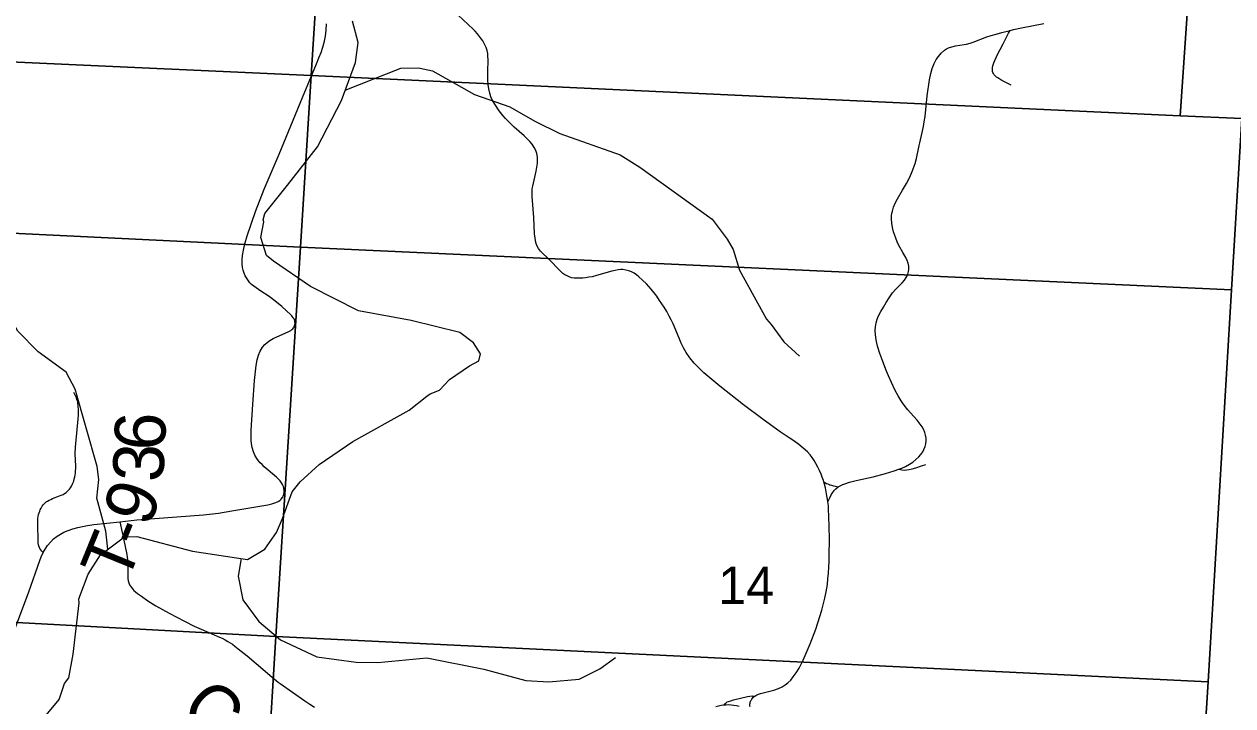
# Model space of a CAD drawing. Extents: x 0 to 34, y 0 to 22.
# Drawn here: x 25.758 to 27.11, y 15.745 to 16.507 of the extents above; entities that cross this region are included whole.
import ezdxf

# ---------------------------------------------------------------- set-up
doc = ezdxf.new("R2010")
doc.units = 0
for name, color, linetype in [('GM_X_County_Road', 7, 'Continuous'), ('GM_X_County_Road_Text', 7, 'Continuous'), ('GM_X_Minor_River', 7, 'Continuous'), ('GM_X_Section', 7, 'Continuous'), ('GM_X_Section_Text', 7, 'Continuous'), ('GM_X_State_Route', 7, 'Continuous'), ('GM_X_Township_Road', 7, 'Continuous'), ('GM_X_Township_Road_Text', 7, 'Continuous')]:
    doc.layers.add(name, color=color, linetype=linetype)

msp = doc.modelspace()

# ---------------------------------------------------------------- linework, layer by layer
at = {"layer": 'GM_X_County_Road'}
for points in [[(26.6568, 15.9731), (26.659, 15.9775), (26.6606, 15.9808), (26.6618, 15.9828), (26.6632, 15.9846), (26.6643, 15.986), (26.6658, 15.9876), (26.6682, 15.9896), (26.6705, 15.9909), (26.6735, 15.9923), (26.6756, 15.9931), (26.6808, 15.9949), (26.6886, 15.9969), (26.7073, 16.001), (26.7212, 16.0045), (26.731, 16.0075), (26.7361, 16.0094), (26.7394, 16.0106), (26.7436, 16.0126), (26.748, 16.0149), (26.7517, 16.0174), (26.7551, 16.0201), (26.7583, 16.0231), (26.7609, 16.0259), (26.763, 16.029), (26.7642, 16.0313), (26.7656, 16.0348), (26.7664, 16.0379), (26.7667, 16.041), (26.7666, 16.0442), (26.7661, 16.0473), (26.7652, 16.0504), (26.764, 16.0533), (26.7622, 16.0566), (26.7589, 16.0612), (26.7566, 16.0641), (26.7492, 16.0725), (26.7463, 16.0758), (26.7422, 16.0811), (26.7404, 16.0835), (26.7388, 16.0859), (26.7352, 16.0916), (26.7321, 16.0975), (26.7279, 16.1064), (26.7247, 16.1138), (26.7225, 16.119), (26.7181, 16.1299), (26.7149, 16.1386), (26.7124, 16.1469), (26.7107, 16.1541), (26.7099, 16.1596), (26.7097, 16.1645), (26.71, 16.1687), (26.7107, 16.1729), (26.7118, 16.177), (26.7134, 16.181), (26.716, 16.1858), (26.7188, 16.1905), (26.722, 16.1958), (26.7253, 16.201), (26.7292, 16.2064), (26.7327, 16.2106), (26.7364, 16.2145), (26.7398, 16.2178), (26.7426, 16.2209), (26.7444, 16.2236), (26.7455, 16.2257), (26.7461, 16.2276), (26.7468, 16.2303), (26.7472, 16.2326), (26.7472, 16.2363), (26.7465, 16.2399), (26.7455, 16.2427), (26.7439, 16.246), (26.7405, 16.2518), (26.7372, 16.2576), (26.7348, 16.2626), (26.7323, 16.2689), (26.7303, 16.2747), (26.7291, 16.2795), (26.7283, 16.2844), (26.728, 16.2892), (26.7281, 16.2929), (26.7283, 16.2953), (26.7289, 16.2977), (26.7303, 16.3024), (26.7321, 16.3069), (26.7347, 16.3118), (26.7404, 16.3213), (26.7448, 16.3288), (26.7485, 16.336), (26.7512, 16.3423), (26.7543, 16.3512), (26.7557, 16.3566), (26.7589, 16.3711), (26.7595, 16.3742), (26.7623, 16.3857), (26.7638, 16.3924), (26.7645, 16.3979), (26.7655, 16.4037), (26.7679, 16.4269), (26.7703, 16.4445), (26.772, 16.4517), (26.7735, 16.4573), (26.7758, 16.463), (26.778, 16.4673), (26.7804, 16.4708), (26.7834, 16.4746), (26.787, 16.4777), (26.7896, 16.4793), (26.7917, 16.4803), (26.7952, 16.4816), (26.7993, 16.4826), (26.8091, 16.484), (26.8116, 16.4845), (26.8157, 16.4856), (26.8193, 16.4868), (26.8346, 16.4926), (26.8395, 16.4943), (26.8448, 16.4959), (26.8511, 16.4976), (26.8605, 16.4999), (26.8644, 16.5009), (26.8734, 16.5027), (26.8981, 16.5077)], [(26.6523, 15.9951), (26.6553, 15.9935), (26.6577, 15.9925), (26.6591, 15.9919), (26.6608, 15.9914), (26.6631, 15.9908), (26.6654, 15.9903), (26.6682, 15.9896)], [(25.865, 15.9506), (25.8676, 15.9386), (25.8706, 15.9247), (25.8729, 15.9142), (25.8734, 15.9112), (25.8738, 15.9086), (25.874, 15.9056), (25.8741, 15.9025), (25.8741, 15.8897), (25.8742, 15.8871), (25.8745, 15.8846), (25.8751, 15.8822), (25.8759, 15.8803), (25.8769, 15.8785), (25.8781, 15.877), (25.8795, 15.8754), (25.8809, 15.8739), (25.8826, 15.8724), (25.8847, 15.8706), (25.8892, 15.8673), (25.8964, 15.8624), (25.9053, 15.8568), (25.9204, 15.8483), (25.9373, 15.8395), (25.9484, 15.834), (25.956, 15.8304), (25.9707, 15.8243), (25.9741, 15.8229), (25.9767, 15.8218), (25.9795, 15.8204), (25.9828, 15.8187), (25.986, 15.8169), (25.9886, 15.8153), (25.991, 15.8137), (25.9938, 15.8116), (25.9973, 15.8087), (26.0074, 15.8007), (26.0177, 15.7921), (26.0355, 15.7768), (26.0376, 15.775), (26.0398, 15.7732), (26.0421, 15.7715), (26.0442, 15.7699), (26.072, 15.7504), (26.0776, 15.7466), (26.0826, 15.7435)], [(26.5316, 15.744), (26.5344, 15.7449), (26.5373, 15.7455), (26.5405, 15.7459), (26.5428, 15.7461), (26.5454, 15.7462), (26.5486, 15.7461), (26.5517, 15.7457), (26.5547, 15.7452), (26.5576, 15.7446)], [(26.5405, 15.7459), (26.5418, 15.7474), (26.5429, 15.7483), (26.5443, 15.7492), (26.5456, 15.7498), (26.5482, 15.7506), (26.5511, 15.7514), (26.5668, 15.7552), (26.5694, 15.7557), (26.5721, 15.756), (26.5752, 15.7558)]]:
    msp.add_lwpolyline(points, dxfattribs=at)
at = {"layer": 'GM_X_Minor_River'}
for points in [[(25.779, 15.73), (25.7971, 15.7521), (25.8031, 15.77), (25.808, 15.7761), (25.8129, 15.8027), (25.8197, 15.8601), (25.8193, 15.8643), (25.8298, 15.892), (25.8434, 15.9137), (25.8702, 15.9339), (25.8842, 15.934), (25.9462, 15.9178), (26.0079, 15.9085), (26.0271, 15.9199), (26.0403, 15.9386), (26.0471, 15.9542), (26.0577, 15.9842), (26.0668, 15.9953), (26.0879, 16.0147), (26.1257, 16.0403), (26.1888, 16.0754), (26.2084, 16.091), (26.2122, 16.0937), (26.2224, 16.0979), (26.2337, 16.1097), (26.256, 16.125), (26.2666, 16.1307), (26.2685, 16.1383), (26.2605, 16.1508), (26.2454, 16.1622), (26.191, 16.1757), (26.132, 16.1866), (26.0783, 16.2138), (26.037, 16.2418), (26.0291, 16.2483), (26.0227, 16.2684), (26.026, 16.2859), (26.0253, 16.2882), (26.0272, 16.2954), (26.0525, 16.327), (26.0861, 16.3697), (26.1129, 16.4214), (26.1287, 16.464), (26.1317, 16.4865), (26.1253, 16.5104)], [(25.8517, 15.9199), (25.8493, 15.9401), (25.8395, 15.9769), (25.8416, 15.9977), (25.8398, 16.0125), (25.8152, 16.0987), (25.8052, 16.1177), (25.7738, 16.1407), (25.751, 16.1638), (25.7277, 16.2055), (25.7205, 16.2183), (25.6953, 16.2461), (25.676, 16.2569), (25.6365, 16.2878), (25.5914, 16.334), (25.575, 16.3421), (25.5444, 16.3674), (25.5396, 16.3713), (25.527, 16.3926), (25.5105, 16.4079), (25.4978, 16.4251), (25.462, 16.4531)], [(26.1172, 16.4331), (26.1792, 16.4577), (26.1992, 16.4582), (26.2146, 16.4547), (26.2618, 16.4282), (26.3011, 16.4144), (26.3293, 16.3983), (26.3569, 16.3845), (26.4246, 16.3607), (26.4465, 16.3471), (26.5275, 16.2891), (26.5442, 16.2666), (26.551, 16.2549), (26.5579, 16.2319), (26.5883, 16.1771), (26.5934, 16.1712), (26.6076, 16.1518), (26.6249, 16.1357)], [(26.0009, 15.9095), (25.9976, 15.8898), (26.0026, 15.8632), (26.0204, 15.8393), (26.0448, 15.8185), (26.0854, 15.7996), (26.1294, 15.7936), (26.1537, 15.7933), (26.2083, 15.7987), (26.272, 15.7859), (26.3191, 15.7731), (26.3449, 15.7717), (26.3786, 15.7748), (26.4017, 15.7862), (26.4192, 15.7988)]]:
    msp.add_lwpolyline(points, dxfattribs=at)
at = {"layer": 'GM_X_Section'}
for points in [[(27.1786, 17.2427), (27.1198, 16.4014), (27.0508, 16.4046), (27.0684, 16.6654), (27.1074, 17.2433)], [(25.1282, 16.7564), (25.9113, 16.7209), (26.0957, 16.7125), (26.0791, 16.4497), (25.1102, 16.4936)], [(26.0957, 16.7125), (26.5448, 16.6908), (27.0684, 16.6654), (27.0508, 16.4046), (26.0791, 16.4497)], [(25.1102, 16.4936), (26.0791, 16.4497), (26.067, 16.2576), (25.0369, 16.3074), (25.0486, 16.498)], [(27.0508, 16.4046), (27.1198, 16.4014), (27.1082, 16.21), (26.067, 16.2576), (26.0791, 16.4497)], [(25.0369, 16.3074), (26.067, 16.2576), (26.0395, 15.8225), (25.0112, 15.8778)], [(26.067, 16.2576), (27.1082, 16.21), (27.0819, 15.7717), (26.0395, 15.8225)], [(26.0395, 15.8225), (26.0137, 15.3999), (24.9883, 15.4512), (25.0112, 15.8778)], [(27.0819, 15.7717), (27.0537, 15.3245), (26.2501, 15.3844), (26.0137, 15.3999), (26.0395, 15.8225)]]:
    msp.add_lwpolyline(points, close=True, dxfattribs=at)
msp.add_lwpolyline([(27.7971, 15.2681), (27.0537, 15.3245), (27.0819, 15.7717), (27.1082, 16.21), (27.1198, 16.4014)], dxfattribs=at)
at = {"layer": 'GM_X_State_Route'}
for points in [[(26.5698, 15.7439), (26.5697, 15.745), (26.5696, 15.746), (26.5697, 15.7469), (26.5698, 15.7479), (26.57, 15.7489), (26.5703, 15.7498), (26.5707, 15.7507), (26.5712, 15.7516), (26.5718, 15.7525), (26.5725, 15.7535), (26.5734, 15.7544), (26.5743, 15.7552), (26.5752, 15.7558), (26.5764, 15.7566), (26.5775, 15.7572), (26.5785, 15.7576), (26.5793, 15.7579), (26.5804, 15.7583), (26.5815, 15.7586), (26.5963, 15.7625), (26.6017, 15.7644), (26.6057, 15.7662), (26.609, 15.7682), (26.612, 15.7706), (26.6152, 15.7737), (26.618, 15.7771), (26.6213, 15.7817), (26.6245, 15.7871), (26.629, 15.796), (26.637, 15.8143), (26.6433, 15.8305), (26.65, 15.8518), (26.6534, 15.8652), (26.6549, 15.8724), (26.6562, 15.8806), (26.6569, 15.8867), (26.6574, 15.893), (26.6579, 15.8998), (26.6582, 15.9062), (26.6584, 15.9123), (26.6585, 15.9319), (26.658, 15.9571), (26.6576, 15.9639), (26.6573, 15.9684), (26.6568, 15.9731), (26.6564, 15.976), (26.6558, 15.9798), (26.655, 15.9841), (26.654, 15.9886), (26.6529, 15.9927), (26.6523, 15.9951), (26.6518, 15.9966), (26.6505, 16.0004), (26.6492, 16.0038), (26.6474, 16.0078), (26.6456, 16.0117), (26.6434, 16.0158), (26.6415, 16.0192), (26.6393, 16.0224), (26.6369, 16.0256), (26.6339, 16.0288), (26.6293, 16.0331), (26.6244, 16.037), (26.6188, 16.041), (26.6136, 16.0444), (26.6033, 16.0513), (26.5843, 16.0651), (26.5626, 16.0813), (26.536, 16.1022), (26.5182, 16.1173), (26.5125, 16.1226), (26.5073, 16.128), (26.5024, 16.1339), (26.4982, 16.1399), (26.4953, 16.1449), (26.4928, 16.1502), (26.4904, 16.1558), (26.4837, 16.1719), (26.4815, 16.1765), (26.4795, 16.1805), (26.4766, 16.1856), (26.4737, 16.1904), (26.4712, 16.1944), (26.4687, 16.1981), (26.4654, 16.2028), (26.4625, 16.2067), (26.4593, 16.2105), (26.4539, 16.2165), (26.4496, 16.2207), (26.4455, 16.2244), (26.4428, 16.2267), (26.4402, 16.2284), (26.4373, 16.2299), (26.4341, 16.2312), (26.4308, 16.232), (26.4277, 16.2325), (26.4252, 16.2326), (26.4223, 16.2323), (26.4188, 16.2317), (26.4153, 16.2309), (26.3981, 16.2258), (26.3931, 16.2246), (26.3894, 16.2239), (26.3859, 16.2234), (26.3827, 16.223), (26.3793, 16.2228), (26.3761, 16.2228), (26.3731, 16.2231), (26.3702, 16.2235), (26.3677, 16.2244), (26.3651, 16.2254), (26.3627, 16.2267), (26.3605, 16.2283), (26.3586, 16.2299), (26.3562, 16.2322), (26.346, 16.2429), (26.3355, 16.2533), (26.3332, 16.2561), (26.3315, 16.2593), (26.3301, 16.2628), (26.3294, 16.2676), (26.3289, 16.2725), (26.3281, 16.2907), (26.3262, 16.3144), (26.326, 16.3172), (26.326, 16.32), (26.3263, 16.3228), (26.3268, 16.3257), (26.3307, 16.3426), (26.3315, 16.3472), (26.332, 16.3516), (26.3322, 16.3552), (26.332, 16.3583), (26.3312, 16.3623), (26.3301, 16.3657), (26.3284, 16.3691), (26.326, 16.3728), (26.3237, 16.3757), (26.3211, 16.3783), (26.3172, 16.382), (26.306, 16.3919), (26.3026, 16.395), (26.2993, 16.3984), (26.2964, 16.4014), (26.2938, 16.4045), (26.2893, 16.4102), (26.2851, 16.4164), (26.2819, 16.4217), (26.2801, 16.4258), (26.2788, 16.4299), (26.2777, 16.4345), (26.277, 16.4396), (26.2767, 16.4444), (26.2766, 16.4491), (26.2766, 16.4531), (26.2769, 16.4674), (26.2767, 16.4707), (26.2764, 16.4743), (26.2757, 16.4775), (26.2746, 16.4807), (26.2734, 16.4837), (26.271, 16.4881), (26.2685, 16.4918), (26.2651, 16.4961), (26.2624, 16.499), (26.26, 16.5014), (26.2379, 16.5223)], [(25.7486, 15.8324), (25.7632, 15.8724), (25.7755, 15.9072), (25.7772, 15.9115), (25.7793, 15.9162), (25.7816, 15.9201), (25.7843, 15.9241), (25.7878, 15.9282), (25.7911, 15.9315), (25.795, 15.9345), (25.7986, 15.9368), (25.8025, 15.9389), (25.8073, 15.941), (25.8124, 15.9427), (25.8183, 15.9443), (25.8234, 15.9454), (25.8289, 15.9463), (25.8361, 15.9474), (25.865, 15.9506), (25.8841, 15.9527), (25.9586, 15.9585), (25.9753, 15.9604), (25.9902, 15.9627), (26.0307, 15.9697), (26.0351, 15.9708), (26.0386, 15.9718), (26.0413, 15.973), (26.0428, 15.9738), (26.0442, 15.9748), (26.0456, 15.976), (26.0469, 15.9776), (26.0479, 15.9793), (26.0485, 15.9812), (26.0489, 15.9836), (26.0489, 15.9858), (26.0486, 15.9878), (26.048, 15.99), (26.0471, 15.9922), (26.046, 15.9943), (26.0445, 15.9964), (26.0427, 15.9984), (26.0404, 16.0006), (26.0266, 16.012), (26.0241, 16.0145), (26.0221, 16.0166), (26.0202, 16.0189), (26.0183, 16.0214), (26.0162, 16.0252), (26.0146, 16.0289), (26.0132, 16.0335), (26.0123, 16.0379), (26.012, 16.042), (26.0119, 16.0464), (26.012, 16.0531), (26.014, 16.0819), (26.0158, 16.1084), (26.0167, 16.1187), (26.0176, 16.1255), (26.0188, 16.1318), (26.0201, 16.1368), (26.0222, 16.1415), (26.0246, 16.1457), (26.0271, 16.1487), (26.0297, 16.1511), (26.033, 16.1533), (26.0366, 16.1554), (26.0407, 16.1573), (26.0532, 16.1628), (26.0548, 16.1636), (26.0562, 16.1646), (26.0576, 16.1656), (26.0585, 16.1664), (26.0593, 16.1674), (26.0599, 16.1682), (26.0602, 16.169), (26.0606, 16.17), (26.0609, 16.1712), (26.061, 16.1725), (26.0609, 16.1739), (26.0608, 16.1752), (26.0604, 16.1763), (26.0599, 16.1775), (26.0591, 16.1786), (26.0583, 16.1798), (26.0574, 16.1809), (26.0563, 16.1821), (26.0463, 16.1913), (26.0385, 16.1976), (26.0319, 16.2024), (26.0226, 16.2086), (26.0151, 16.2139), (26.0125, 16.216), (26.0106, 16.2178), (26.0088, 16.2198), (26.0073, 16.2221), (26.0054, 16.2255), (26.0041, 16.2285), (26.003, 16.2319), (26.0024, 16.2348), (26.002, 16.239), (26.002, 16.2433), (26.0024, 16.2482), (26.0034, 16.2543), (26.005, 16.2615), (26.0076, 16.2704), (26.0169, 16.2975), (26.0265, 16.3224), (26.0434, 16.3617), (26.0692, 16.425), (26.0851, 16.4624), (26.0878, 16.4691), (26.0901, 16.4753), (26.0921, 16.4813), (26.0939, 16.4879), (26.095, 16.4934), (26.0959, 16.5003), (26.0963, 16.5072)]]:
    msp.add_lwpolyline(points, dxfattribs=at)
at = {"layer": 'GM_X_Township_Road'}
for points in [[(26.8617, 16.4387), (26.8514, 16.4441), (26.8468, 16.4468), (26.8452, 16.4478), (26.8437, 16.4491), (26.8427, 16.4503), (26.8418, 16.4516), (26.8413, 16.4527), (26.8409, 16.4539), (26.8407, 16.4555), (26.8407, 16.4568), (26.8408, 16.4585), (26.8412, 16.4603), (26.8423, 16.4636), (26.8462, 16.4721), (26.8527, 16.4849), (26.8589, 16.4969), (26.8605, 16.4999)], [(25.7793, 15.9162), (25.7778, 15.9178), (25.7767, 15.9193), (25.7757, 15.9208), (25.7748, 15.9227), (25.7742, 15.925), (25.7739, 15.9276), (25.7737, 15.9305), (25.7733, 15.9468), (25.7733, 15.9496), (25.7733, 15.9519), (25.7735, 15.9542), (25.7737, 15.9565), (25.7743, 15.9587), (25.7748, 15.9606), (25.7755, 15.9625), (25.7762, 15.964), (25.7771, 15.9658), (25.7784, 15.968), (25.7794, 15.9694), (25.7804, 15.9706), (25.7816, 15.9718), (25.7829, 15.9729), (25.7844, 15.9738), (25.786, 15.9748), (25.788, 15.9757), (25.79, 15.9766), (25.7977, 15.9795), (25.7997, 15.9802), (25.8017, 15.9812), (25.8033, 15.9821), (25.805, 15.9833), (25.8064, 15.9844), (25.8078, 15.9858), (25.809, 15.9872), (25.8101, 15.9887), (25.811, 15.9905), (25.8119, 15.9921), (25.8127, 15.9939), (25.8135, 15.9962), (25.8142, 15.9985), (25.8148, 16.001), (25.8153, 16.0029), (25.8156, 16.0051), (25.8157, 16.0074), (25.8158, 16.0103), (25.8158, 16.0131), (25.8152, 16.0263), (25.8153, 16.0291), (25.8154, 16.0319), (25.8156, 16.0343), (25.8159, 16.0379), (25.8186, 16.0656), (25.8188, 16.0694), (25.8189, 16.0729), (25.8188, 16.0762), (25.8187, 16.079), (25.8185, 16.0811), (25.8182, 16.083), (25.818, 16.0846), (25.8176, 16.0861), (25.8172, 16.0875), (25.8167, 16.089), (25.816, 16.0905), (25.8148, 16.093), (25.8135, 16.0952)], [(26.7361, 16.0094), (26.7394, 16.0088), (26.7423, 16.0085), (26.7449, 16.0086), (26.7477, 16.009), (26.751, 16.0098), (26.7553, 16.011), (26.7613, 16.013), (26.7663, 16.0146)]]:
    msp.add_lwpolyline(points, dxfattribs=at)

# ---------------------------------------------------------------- texts
at = {"layer": 'GM_X_County_Road_Text'}
msp.add_text('C', height=0.0568, rotation=318.857, dxfattribs=at).set_placement((25.9306, 15.7372))
at = {"layer": 'GM_X_Section_Text'}
msp.add_text('14', height=0.04186, rotation=0, dxfattribs=at).set_placement((26.5343, 15.8587))
at = {"layer": 'GM_X_Township_Road_Text'}
for s, rotation, p in [('6', 87.3367, (25.9152, 16.0294)), ('3', 87.3, (25.9135, 15.9944)), ('9', 70.4444, (25.8983, 15.9436)), ('-', 68.0876, (25.8887, 15.9196)), ('T', 67.7744, (25.8725, 15.8799))]:
    msp.add_text(s, height=0.0568, rotation=rotation, dxfattribs=at).set_placement(p)

doc.saveas('drawing.dxf')
